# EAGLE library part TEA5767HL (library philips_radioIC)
Philips TEA576* Single Chip FM Receiver Supports TEA5767HL and TEA5768HL TEA5767 = 3-Wire Bus model TEA5768 = I2c Bus model The schematic symbol for this device was originally designed for the TEA5767HL but has been updated to support the TEA5768. Essentially there are 4 pins allocated on each chip for I/O and each had the same names practically. Chip includes all neccessary functions of a complete fm receiver No tunable parts are neccessary upon manufacturing
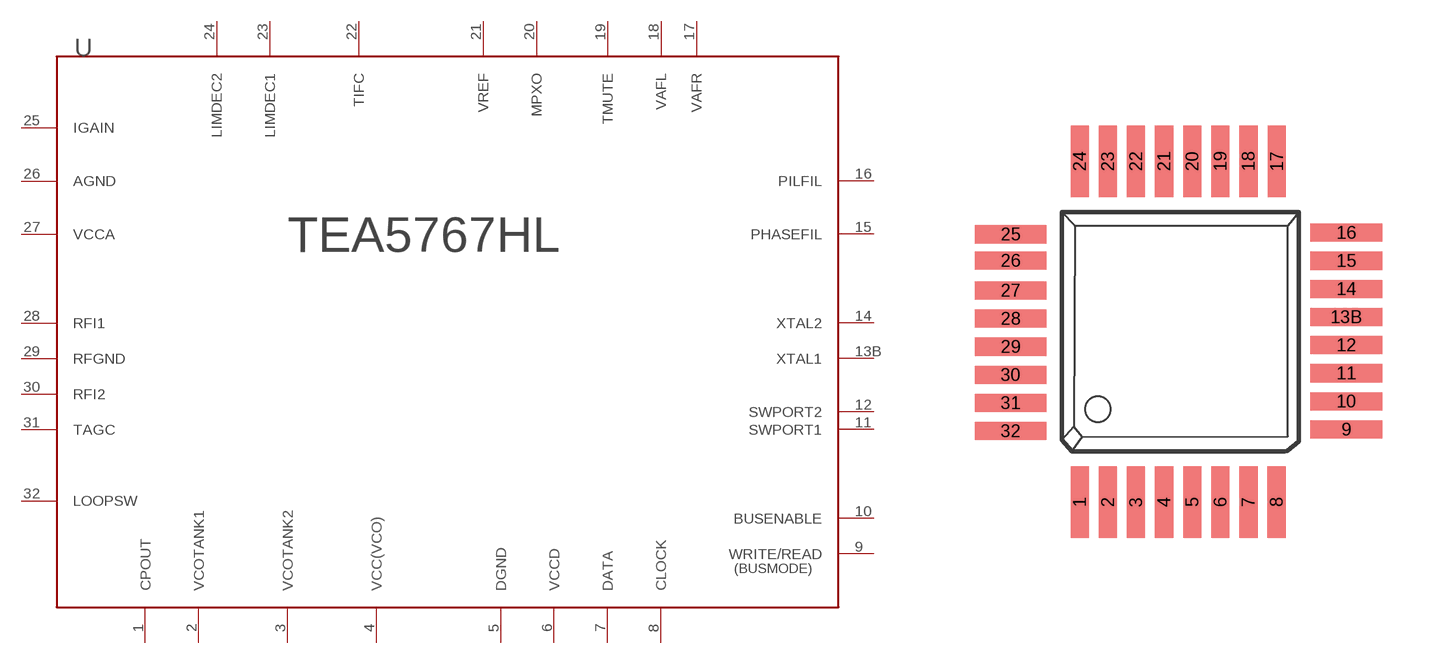
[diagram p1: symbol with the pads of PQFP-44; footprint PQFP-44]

Designator prefix -

## TEA5767HLFP  [PQFP-44]
1  CPOUT
2  VCOTANK1
3  VCOTANK2
4  VCC(VCO)
5  DGND  pwr
6  VCCD  pwr
7  DATA
8  CLOCK  in
9  WRITE/READ  in
10  BUSENABLE  in
11  SWPORT1
12  SWPORT2
13B  XTAL1  pas
14  XTAL2  pas
15  PHASEFIL  pas
16  PILFIL  pas
17  VAFR  out
18  VAFL  out
19  TMUTE  pas
20  MPXO  out
21  VREF  pas
22  TIFC  pas
23  LIMDEC1  pas
24  LIMDEC2  pas
25  IGAIN  pas
26  AGND  pwr
27  VCCA  pwr
28  RFI1  in
29  RFGND  pwr
30  RFI2  in
31  TAGC  pas
32  LOOPSW  in

## Footprint PQFP-44 (pad centres in mm)
32 Pin Plastic Quad Flat Pack created by Blake Robertson
smd 0.508 x 2.007: 1 -3.937,-6.706; 2 -3.15,-6.706; 3 -2.362,-6.706; 4 -1.575,-6.706; 5 -0.787,-6.706; 6 0,-6.706; 7 0.787,-6.706; 8 1.575,-6.706; 17 1.584,2.84; 18 0.787,2.844; 19 0,2.844; 20 -0.787,2.844; 21 -1.575,2.844; 22 -2.362,2.844; 23 -3.15,2.844; 24 -3.937,2.844
smd 2.007 x 0.508: 9 3.525,-4.668; 10 3.525,-3.881; 11 3.525,-3.094; 12 3.525,-2.306; 13B 3.525,-1.519; 14 3.525,-0.731; 15 3.525,0.056; 16 3.525,0.844; 25 -5.875,0.798; 26 -5.875,0.061; 27 -5.875,-0.776; 28 -5.875,-1.564; 29 -5.875,-2.351; 30 -5.875,-3.139; 31 -5.875,-3.926; 32 -5.875,-4.714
